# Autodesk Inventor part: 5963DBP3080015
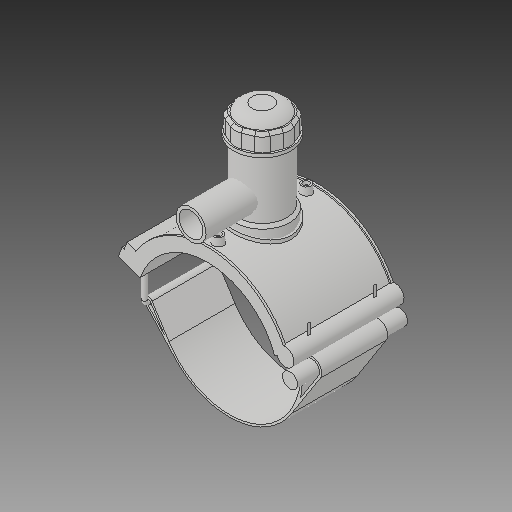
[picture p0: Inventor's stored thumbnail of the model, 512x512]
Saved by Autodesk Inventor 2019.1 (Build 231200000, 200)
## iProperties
Created: 2017-07
Part Number: 5963DBP3080015
Material: Generic
Description: PLASSON TAPPING SADDLE 8''DIPS x 1 1/2''IPS
Document SubType Name: Modeling
Designer: KIM
Density: 1 g/cm^3
Appearance: Default
Author: KIM
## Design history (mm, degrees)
derived "5963DBP_5963BUP.ipt"
feature "Solid1::5963DBP_5963BUP.ipt"
feature "Solid2::5963DBP_5963BUP.ipt"
feature "Solid3::5963DBP_5963BUP.ipt"
tag "TaggingFeature1"
body "Solid1"
body "Solid2"
body "Solid3"
other parameters: "d0" = 228.9, "d2" = 269.748, "d3" = 57.225, "d4" = 176.022, "d5" = 0, "d6" = 0.1, "d8" = 0, "d19" = 6, "d20" = 6, "d21" = 105.6132, "d23" = 0, "d24" = 52.8066, "d26" = 0, "d27" = 3, "d28" = 3, "d29" = 3, "d30" = 76.3, "d31" = 6, "d32" = 0, "d33" = 0, "d34" = 0.6, "d40" = 138.07248, "d41" = 91.56, "d43" = 0, "d45" = 0, "d47" = 238.3752, "d70" = 15, "d72" = 0, "d73" = 6, "d75" = 5, "d76" = 0, "d77" = 11.445, "d78" = 144.45, "d79" = 15, "d80" = 70.4088, "d82" = 5 deg, "d84" = 4, "d85" = 14, "d86" = 0, "d87" = 3, "d88" = 0, "d89" = 1, "d90" = 1, "d91" = 140.8176, "d92" = 0, "d93" = 0.5, "d94" = 120.47368, "d96" = 270.83448, "d97" = 3.52044, "d98" = 0, "d120" = 140 deg, "d121" = 24.228, "d122" = 20 deg, "d123" = 531.048, "d124" = 159.3144, "d126" = 0, "d143" = 235.767, "d145" = 28.17231, "d149" = 3.4335, "d150" = 30.98954, "d153" = 176.022, "d154" = 0, "d156" = 132.762, "d157" = 160 deg, "d159" = 7.3248, "d161" = 3.4335, "d162" = 105.6132, "d163" = 0, "d164" = 114.45, "d167" = 22.89, "d168" = 129.5239, "d170" = 3.4335, "d172" = 0, "d173" = 1, "d175" = 114.45, "d176" = 20 deg, "d177" = 16.023, "d178" = 36.624, "d180" = 0, "d183" = 14.6496, "d184" = 12.8184, "d185" = 57.20715, "d186" = 57.20715, "d187" = 132.762, "d188" = 10.9872, "d189" = 16.023, "d190" = 0, "d191" = 199.143, "d193" = 7.3248, "d194" = 6.16077, "d195" = 90 deg, "d197" = 0, "d199" = 0, "d200" = 18.312, "d202" = 0, "d203" = 177.038, "d204" = 86.982, "d205" = 64.092, "d206" = 77.826, "d207" = 132.7785, "d208" = 138.08964, "d209" = 164.64534, "d210" = 78.7416, "d211" = 91.56, "d212" = 73.248, "d213" = 36.8766, "d216" = 0, "d217" = 22.89, "d218" = 22.89, "d219" = 4.578, "d222" = 228.9, "d224" = 0, "d225" = 65.024, "d226" = 48.1, "d227" = 38.48, "d228" = 114.046, "d230" = 4.578, "d_" = 228.9, "B_" = 179.832, "L_" = 176.022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
